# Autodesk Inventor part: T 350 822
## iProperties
Created: 2006-07
Part Number: T 350 822
Document SubType Name: Modeling
Designer: I.Baliuc
Material: 2.0060
Description: Stromband
Density: 8.94 g/cm^3
Author: T.Messerschmitt
Revision Number: 350822
Comments: Model: C - erstellt für Strombahn DC/Schalter
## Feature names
1. Basis1
